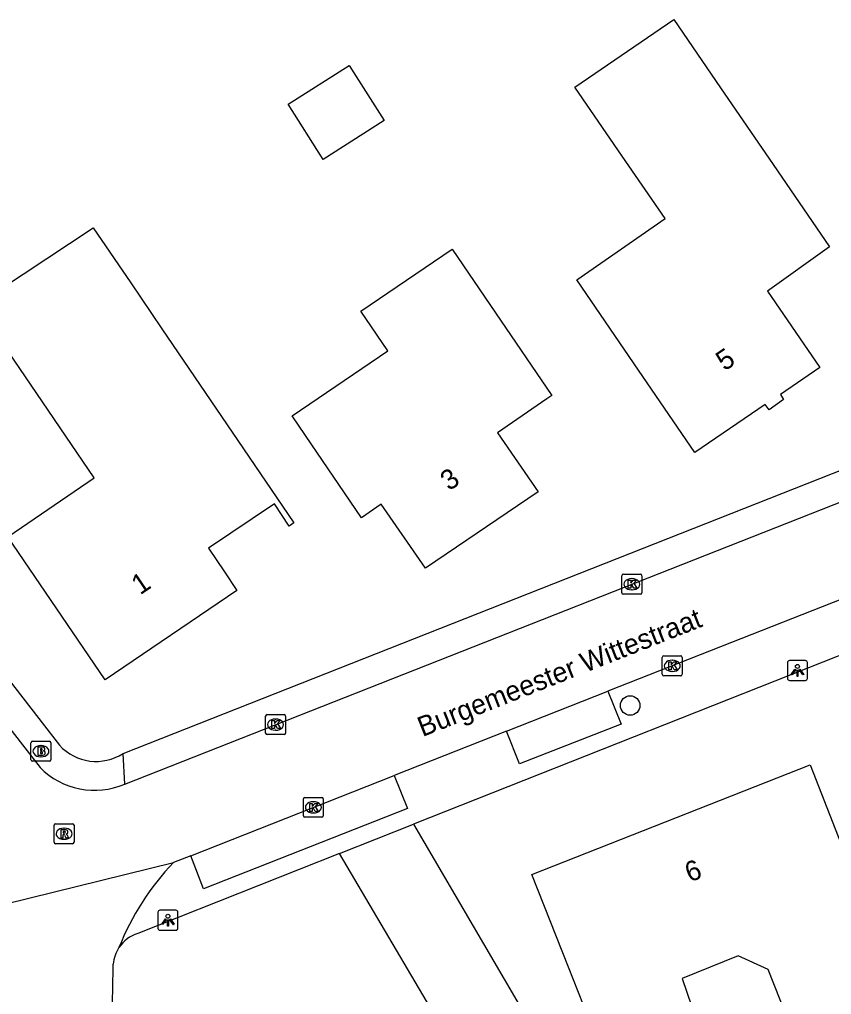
# Model space of a CAD drawing. Extents: x 159503 to 160347, y 382525 to 383272.
# Drawn here: x 159799.95 to 159840.68, y 382910.37 to 382959.27 of the extents above; entities that cross this region are included whole.
import ezdxf

# ---------------------------------------------------------------- set-up
doc = ezdxf.new("R2010")
doc.units = 0
for name, color, linetype in [('IMGEO_Boom', 7, 'Continuous'), ('IMGEO_Brandkraan', 7, 'Continuous'), ('IMGEO_Groenvoorziening', 7, 'Continuous'), ('IMGEO_Kolk', 7, 'Continuous'), ('IMGEO_Lichtpunt', 7, 'Continuous'), ('IMGEO_Openbare_ruimte_label', 7, 'Continuous'), ('IMGEO_Pand', 7, 'Continuous'), ('IMGEO_Pand_nummerreeks', 7, 'Continuous'), ('IMGEO_Rijbaan_lokaal_open', 7, 'Continuous'), ('IMGEO_Rioolput', 7, 'Continuous'), ('IMGEO_Voetpad_open', 7, 'Continuous')]:
    doc.layers.add(name, color=color, linetype=linetype)

msp = doc.modelspace()

# ---------------------------------------------------------------- linework, layer by layer
at = {"layer": 'IMGEO_Boom'}
msp.add_circle((159830.58, 382924.866), 0.489, dxfattribs=at)
at = {"layer": 'IMGEO_Brandkraan'}
for p, q in [((159800.523, 382922.147), (159800.523, 382922.999)), ((159800.598, 382923.073), (159801.45, 382923.073)), ((159801.524, 382922.999), (159801.524, 382922.147)), ((159801.011, 382922.853), (159801.036, 382922.853)), ((159801.45, 382922.073), (159800.598, 382922.073)), ((159801.034, 382922.293), (159801.009, 382922.293))]:
    msp.add_line(p, q, dxfattribs=at)
for points in [[(159800.523, 382922.147), (159800.523, 382922.999)], [(159800.598, 382923.073), (159801.45, 382923.073)], [(159801.524, 382922.999), (159801.524, 382922.147)], [(159800.871, 382922.773), (159800.871, 382922.373), (159801.084, 382922.373)], [(159801.102, 382922.773), (159800.871, 382922.773)], [(159801.05, 382922.692), (159800.996, 382922.692), (159800.996, 382922.616)], [(159800.996, 382922.616), (159801.049, 382922.616)], [(159801.058, 382922.54), (159800.996, 382922.54), (159800.996, 382922.459)], [(159800.996, 382922.459), (159801.058, 382922.459)], [(159801.45, 382922.073), (159800.598, 382922.073)]]:
    msp.add_lwpolyline(points, dxfattribs=at)
for centre, radius, start, end in [((159800.6, 382922.997), 0.0765, 91.552, 178.448), ((159800.6, 382922.997), 0.0765, 91.552, 178.448), ((159801.448, 382922.997), 0.0765, 1.552, 88.448), ((159801.448, 382922.997), 0.0765, 1.552, 88.448), ((159801.051, 382922.654), 0.0379, 267.8285, 90.9355), ((159801.059, 382922.499), 0.0404, 269.8759, 90.5077), ((159801.09, 382922.624), 0.251, 268.6676, 293.5347), ((159801.106, 382922.628), 0.145, 59.4692, 91.5367), ((159801.131, 382922.675), 0.0922, 285.5137, 58.1501), ((159801.136, 382922.483), 0.105, 301.3115, 78.989), ((159800.6, 382922.149), 0.0765, 181.552, 268.448), ((159800.6, 382922.149), 0.0765, 181.552, 268.448), ((159801.448, 382922.149), 0.0765, 271.552, 358.448), ((159801.448, 382922.149), 0.0765, 271.552, 358.448)]:
    msp.add_arc(centre, radius, start, end, dxfattribs=at)
for centre, major_axis, ratio, start_param, end_param in [((159801.01, 382922.573), (-0.387, 0.002), 0.722429, 4.712389, 7.853982), ((159801.035, 382922.573), (-0.39, 0.002), 0.717154, 1.570796, 4.712389)]:
    msp.add_ellipse(centre, major_axis=major_axis, ratio=ratio, start_param=start_param, end_param=end_param, dxfattribs=at)
at = {"layer": 'IMGEO_Groenvoorziening'}
for points in [[(159819.719, 382918.916), (159824.775, 382910.258), (159825.57, 382908.897)], [(159822.273, 382906.815), (159816, 382917.445)]]:
    msp.add_lwpolyline(points, dxfattribs=at)
at = {"layer": 'IMGEO_Kolk'}
for p, q in [((159830.163, 382930.523), (159830.163, 382931.375)), ((159830.238, 382931.449), (159831.09, 382931.449)), ((159830.651, 382931.229), (159830.676, 382931.229)), ((159831.164, 382931.375), (159831.164, 382930.523)), ((159831.09, 382930.449), (159830.238, 382930.449)), ((159830.674, 382930.669), (159830.649, 382930.669)), ((159832.191, 382926.429), (159832.191, 382927.281)), ((159832.266, 382927.355), (159833.118, 382927.355)), ((159833.192, 382927.281), (159833.192, 382926.429)), ((159832.679, 382927.135), (159832.704, 382927.135)), ((159833.118, 382926.355), (159832.266, 382926.355)), ((159832.702, 382926.575), (159832.677, 382926.575)), ((159812.366, 382924.407), (159813.218, 382924.407)), ((159812.291, 382923.481), (159812.291, 382924.333)), ((159812.779, 382924.187), (159812.804, 382924.187)), ((159813.292, 382924.333), (159813.292, 382923.481)), ((159813.218, 382923.407), (159812.366, 382923.407)), ((159812.802, 382923.627), (159812.777, 382923.627)), ((159814.186, 382919.332), (159814.186, 382920.184)), ((159814.261, 382920.258), (159815.113, 382920.258)), ((159814.674, 382920.038), (159814.699, 382920.038)), ((159815.187, 382920.184), (159815.187, 382919.332)), ((159814.697, 382919.478), (159814.672, 382919.478)), ((159815.113, 382919.258), (159814.261, 382919.258))]:
    msp.add_line(p, q, dxfattribs=at)
for points in [[(159830.163, 382930.523), (159830.163, 382931.375)], [(159830.238, 382931.449), (159831.09, 382931.449)], [(159831.164, 382931.375), (159831.164, 382930.523)], [(159830.484, 382931.149), (159830.607, 382931.149), (159830.607, 382930.998), (159830.737, 382931.149), (159830.901, 382931.149), (159830.755, 382930.998), (159830.908, 382930.749), (159830.756, 382930.749), (159830.671, 382930.913), (159830.607, 382930.846), (159830.607, 382930.749), (159830.484, 382930.749), (159830.484, 382931.149)], [(159831.09, 382930.449), (159830.238, 382930.449)], [(159832.191, 382926.429), (159832.191, 382927.281)], [(159832.266, 382927.355), (159833.118, 382927.355)], [(159833.192, 382927.281), (159833.192, 382926.429)], [(159832.512, 382927.055), (159832.635, 382927.055), (159832.635, 382926.904), (159832.765, 382927.055), (159832.929, 382927.055), (159832.783, 382926.904), (159832.936, 382926.655), (159832.784, 382926.655), (159832.699, 382926.819), (159832.635, 382926.752), (159832.635, 382926.655), (159832.512, 382926.655), (159832.512, 382927.055)], [(159833.118, 382926.355), (159832.266, 382926.355)], [(159812.366, 382924.407), (159813.218, 382924.407)], [(159812.291, 382923.481), (159812.291, 382924.333)], [(159812.612, 382924.107), (159812.735, 382924.107), (159812.735, 382923.956), (159812.865, 382924.107), (159813.029, 382924.107), (159812.883, 382923.956), (159813.036, 382923.707), (159812.884, 382923.707), (159812.799, 382923.871), (159812.735, 382923.804), (159812.735, 382923.707), (159812.612, 382923.707), (159812.612, 382924.107)], [(159813.292, 382924.333), (159813.292, 382923.481)], [(159813.218, 382923.407), (159812.366, 382923.407)], [(159814.186, 382919.332), (159814.186, 382920.184)], [(159814.261, 382920.258), (159815.113, 382920.258)], [(159814.507, 382919.958), (159814.63, 382919.958), (159814.63, 382919.807), (159814.76, 382919.958), (159814.924, 382919.958), (159814.778, 382919.807), (159814.931, 382919.558), (159814.779, 382919.558), (159814.694, 382919.722), (159814.63, 382919.655), (159814.63, 382919.558), (159814.507, 382919.558), (159814.507, 382919.958)], [(159815.187, 382920.184), (159815.187, 382919.332)], [(159815.113, 382919.258), (159814.261, 382919.258)]]:
    msp.add_lwpolyline(points, dxfattribs=at)
for centre, start, end in [((159830.24, 382931.373), 91.552, 178.448), ((159830.24, 382931.373), 91.552, 178.448), ((159831.088, 382931.373), 1.552, 88.448), ((159831.088, 382931.373), 1.552, 88.448), ((159830.24, 382930.525), 181.552, 268.448), ((159830.24, 382930.525), 181.552, 268.448), ((159831.088, 382930.525), 271.552, 358.448), ((159831.088, 382930.525), 271.552, 358.448), ((159832.268, 382927.279), 91.552, 178.448), ((159832.268, 382927.279), 91.552, 178.448), ((159833.116, 382927.279), 1.552, 88.448), ((159833.116, 382927.279), 1.552, 88.448), ((159832.268, 382926.431), 181.552, 268.448), ((159832.268, 382926.431), 181.552, 268.448), ((159833.116, 382926.431), 271.552, 358.448), ((159833.116, 382926.431), 271.552, 358.448), ((159812.368, 382924.331), 91.552, 178.448), ((159812.368, 382924.331), 91.552, 178.448), ((159813.216, 382924.331), 1.552, 88.448), ((159813.216, 382924.331), 1.552, 88.448), ((159812.368, 382923.483), 181.552, 268.448), ((159812.368, 382923.483), 181.552, 268.448), ((159813.216, 382923.483), 271.552, 358.448), ((159813.216, 382923.483), 271.552, 358.448), ((159814.263, 382920.182), 91.552, 178.448), ((159814.263, 382920.182), 91.552, 178.448), ((159815.111, 382920.182), 1.552, 88.448), ((159815.111, 382920.182), 1.552, 88.448), ((159814.263, 382919.334), 181.552, 268.448), ((159814.263, 382919.334), 181.552, 268.448), ((159815.111, 382919.334), 271.552, 358.448), ((159815.111, 382919.334), 271.552, 358.448)]:
    msp.add_arc(centre, 0.0765, start, end, dxfattribs=at)
for centre, major_axis, ratio, start_param, end_param in [((159830.65, 382930.949), (-0.387, 0.002), 0.722429, 4.712389, 7.853982), ((159830.675, 382930.949), (-0.39, 0.002), 0.717154, 1.570796, 4.712389), ((159832.678, 382926.855), (-0.387, 0.002), 0.722429, 4.712389, 7.853982), ((159832.703, 382926.855), (-0.39, 0.002), 0.717154, 1.570796, 4.712389), ((159812.778, 382923.907), (-0.387, 0.002), 0.722429, 4.712389, 7.853982), ((159812.803, 382923.907), (-0.39, 0.002), 0.717154, 1.570796, 4.712389), ((159814.673, 382919.758), (-0.387, 0.002), 0.722429, 4.712389, 7.853982), ((159814.698, 382919.758), (-0.39, 0.002), 0.717154, 1.570796, 4.712389)]:
    msp.add_ellipse(centre, major_axis=major_axis, ratio=ratio, start_param=start_param, end_param=end_param, dxfattribs=at)
at = {"layer": 'IMGEO_Lichtpunt'}
for p, q in [((159838.473, 382927.027), (159838.473, 382926.22)), ((159838.473, 382927.027), (159838.473, 382926.22)), ((159839.375, 382927.122), (159838.567, 382927.122)), ((159839.375, 382927.122), (159838.567, 382927.122)), ((159839.469, 382926.22), (159839.469, 382927.027)), ((159839.469, 382926.22), (159839.469, 382927.027)), ((159838.567, 382926.126), (159839.375, 382926.126)), ((159838.567, 382926.126), (159839.375, 382926.126)), ((159807.794, 382914.596), (159806.986, 382914.596)), ((159807.794, 382914.596), (159806.986, 382914.596)), ((159806.892, 382914.501), (159806.892, 382913.694)), ((159806.892, 382914.501), (159806.892, 382913.694)), ((159807.888, 382913.694), (159807.888, 382914.501)), ((159807.888, 382913.694), (159807.888, 382914.501)), ((159806.986, 382913.6), (159807.794, 382913.6)), ((159806.986, 382913.6), (159807.794, 382913.6))]:
    msp.add_line(p, q, dxfattribs=at)
for points in [[(159838.847, 382926.691), (159838.886, 382926.663), (159838.698, 382926.401), (159838.66, 382926.428), (159838.847, 382926.691)], [(159838.949, 382926.643), (159838.996, 382926.643), (159838.996, 382926.321), (159838.949, 382926.321), (159838.949, 382926.643)], [(159839.059, 382926.663), (159839.097, 382926.69), (159839.284, 382926.428), (159839.245, 382926.4), (159839.059, 382926.663)], [(159807.266, 382914.165), (159807.305, 382914.137), (159807.117, 382913.875), (159807.079, 382913.902), (159807.266, 382914.165)], [(159807.368, 382914.117), (159807.415, 382914.117), (159807.415, 382913.795), (159807.368, 382913.795), (159807.368, 382914.117)], [(159807.478, 382914.137), (159807.516, 382914.164), (159807.703, 382913.902), (159807.664, 382913.874), (159807.478, 382914.137)]]:
    msp.add_lwpolyline(points, dxfattribs=at)
for centre in [(159838.972, 382926.825), (159807.391, 382914.299)]:
    msp.add_circle(centre, 0.0994, dxfattribs=at)
for centre, start, end in [((159838.567, 382927.027), 90, 180), ((159838.567, 382927.027), 90, 180), ((159839.375, 382927.027), 0, 90), ((159839.375, 382927.027), 0, 90), ((159838.567, 382926.22), 180, 270), ((159838.567, 382926.22), 180, 270), ((159839.375, 382926.22), 270, 0), ((159839.375, 382926.22), 270, 360), ((159806.986, 382914.501), 90, 180), ((159806.986, 382914.501), 90, 180), ((159807.794, 382914.501), 0, 90), ((159807.794, 382914.501), 0, 90), ((159806.986, 382913.694), 180, 270), ((159806.986, 382913.694), 180, 270), ((159807.794, 382913.694), 270, 0), ((159807.794, 382913.694), 270, 360)]:
    msp.add_arc(centre, 0.0946, start, end, dxfattribs=at)
at = {"layer": 'IMGEO_Pand'}
for points in [[(159832.762, 382959.268), (159835.116, 382955.835), (159837.748, 382951.997), (159840.576, 382947.873), (159837.474, 382945.651), (159840.098, 382941.809), (159838.121, 382940.456), (159838.275, 382940.209), (159837.549, 382939.692), (159837.359, 382939.953), (159833.819, 382937.55), (159831, 382941.681), (159827.903, 382946.22), (159832.335, 382949.291), (159830.175, 382952.411), (159827.804, 382955.868), (159832.762, 382959.268)], [(159816.49, 382956.966), (159818.245, 382954.196), (159815.182, 382952.255), (159813.426, 382955.025), (159816.49, 382956.966)], [(159807.09, 382943.762), (159810.9, 382938.157), (159813.711, 382934.022), (159813.481, 382933.854), (159812.732, 382934.98), (159809.429, 382932.761), (159810.232, 382931.566), (159810.856, 382930.637), (159804.242, 382926.147), (159799.36, 382933.326), (159803.7, 382936.281), (159799.681, 382942.183), (159797.796, 382944.952), (159803.648, 382948.828), (159805.528, 382946.062), (159807.09, 382943.762)], [(159826.646, 382940.418), (159826.404, 382940.241), (159823.924, 382938.546), (159825.958, 382935.584), (159820.316, 382931.756), (159818.093, 382934.961), (159817.109, 382934.282), (159814.294, 382938.414), (159813.628, 382939.392), (159818.417, 382942.652), (159817.066, 382944.633), (159821.648, 382947.753), (159823.831, 382944.55), (159826.646, 382940.418)], [(159846.866, 382903.296), (159840.225, 382900.649), (159837.9, 382906.568), (159838.747, 382908.507), (159837.494, 382911.622), (159836, 382912.309), (159833.186, 382911.18), (159833.664, 382909.806), (159828.984, 382907.938), (159827.481, 382911.745), (159825.644, 382916.395), (159839.605, 382921.884), (159841.424, 382917.227), (159846.866, 382903.296)]]:
    msp.add_lwpolyline(points, dxfattribs=at)
at = {"layer": 'IMGEO_Rijbaan_lokaal_open'}
for points in [[(159773.929, 382959.054), (159781.987, 382948.65), (159795.756, 382930.872), (159801.595, 382923.334), (159801.952, 382922.871)], [(159772.631, 382958.244), (159800.442, 382922.436), (159800.976, 382921.759)], [(159805.148, 382922.46), (159871.857, 382948.784)], [(159805.224, 382920.924), (159850.691, 382938.839)], [(159846.419, 382932.259), (159829.466, 382925.58)], [(159824.384, 382923.582), (159829.466, 382925.58)], [(159824.384, 382923.582), (159818.738, 382921.356)], [(159805.224, 382920.924), (159805.148, 382922.46)], [(159808.536, 382917.335), (159818.738, 382921.356)], [(159808.536, 382917.335), (159807.664, 382916.991)], [(159798.017, 382914.622), (159807.664, 382916.991)]]:
    msp.add_lwpolyline(points, dxfattribs=at)
for centre, radius, start, end in [((159803.794, 382924.566), 2.504, 222.6159, 302.7282), ((159803.714, 382924.467), 3.851, 224.6802, 293.0789), ((159817.242, 382907.863), 13.231, 136.3787, 158.4499), ((159806.437, 382911.725), 1.802, 146.3718, 174.3912), ((159750.82, 382912.013), 53.823, 352.4298, 359.881)]:
    msp.add_arc(centre, radius, start, end, dxfattribs=at)
at = {"layer": 'IMGEO_Rioolput'}
for p, q in [((159801.681, 382918.009), (159801.681, 382918.861)), ((159801.756, 382918.935), (159802.608, 382918.935)), ((159802.169, 382918.715), (159802.194, 382918.715)), ((159802.682, 382918.861), (159802.682, 382918.009)), ((159802.192, 382918.155), (159802.167, 382918.155)), ((159802.608, 382917.935), (159801.756, 382917.935))]:
    msp.add_line(p, q, dxfattribs=at)
for points in [[(159801.681, 382918.009), (159801.681, 382918.861)], [(159801.756, 382918.935), (159802.608, 382918.935)], [(159802.27, 382918.633), (159802.018, 382918.635), (159802.018, 382918.235)], [(159802.196, 382918.554), (159802.142, 382918.554), (159802.142, 382918.473)], [(159802.142, 382918.473), (159802.194, 382918.473)], [(159802.682, 382918.861), (159802.682, 382918.009)], [(159802.018, 382918.235), (159802.142, 382918.235), (159802.142, 382918.397), (159802.153, 382918.397)], [(159802.2, 382918.368), (159802.271, 382918.235), (159802.411, 382918.235), (159802.346, 382918.361)], [(159802.608, 382917.935), (159801.756, 382917.935)]]:
    msp.add_lwpolyline(points, dxfattribs=at)
for centre, radius, start, end in [((159801.758, 382918.859), 0.0765, 91.552, 178.448), ((159801.758, 382918.859), 0.0765, 91.552, 178.448), ((159802.178, 382918.662), 0.19, 274.7715, 282.9687), ((159802.202, 382918.458), 0.0964, 77.0061, 93.1865), ((159802.216, 382918.515), 0.0378, 276.6634, 79.6772), ((159802.269, 382918.523), 0.109, 350.3612, 89.416), ((159802.267, 382918.523), 0.112, 277.5842, 350.9817), ((159802.606, 382918.859), 0.0765, 1.552, 88.448), ((159802.606, 382918.859), 0.0765, 1.552, 88.448), ((159801.758, 382918.011), 0.0765, 181.552, 268.448), ((159801.758, 382918.011), 0.0765, 181.552, 268.448), ((159802.152, 382918.344), 0.0533, 26.0293, 88.6989), ((159802.251, 382918.308), 0.108, 29.5134, 73.7905), ((159802.606, 382918.011), 0.0765, 271.552, 358.448), ((159802.606, 382918.011), 0.0765, 271.552, 358.448)]:
    msp.add_arc(centre, radius, start, end, dxfattribs=at)
for centre, major_axis, ratio, start_param, end_param in [((159802.168, 382918.435), (-0.387, 0.002), 0.722429, 4.712389, 7.853982), ((159802.193, 382918.435), (-0.39, 0.002), 0.717154, 1.570796, 4.712389)]:
    msp.add_ellipse(centre, major_axis=major_axis, ratio=ratio, start_param=start_param, end_param=end_param, dxfattribs=at)
at = {"layer": 'IMGEO_Voetpad_open'}
for points in [[(159876.5, 382941.374), (159819.719, 382918.916)], [(159829.466, 382925.58), (159830.133, 382923.927), (159825.032, 382921.94), (159824.384, 382923.582)], [(159818.738, 382921.356), (159819.408, 382919.703), (159809.177, 382915.674), (159808.536, 382917.335)], [(159816, 382917.445), (159819.719, 382918.916)], [(159816, 382917.445), (159805.876, 382913.439)]]:
    msp.add_lwpolyline(points, dxfattribs=at)
msp.add_arc((159806.442, 382911.721), 1.809, 108.2338, 146.3594, dxfattribs=at)

# ---------------------------------------------------------------- texts
at = {"layer": 'IMGEO_Openbare_ruimte_label'}
msp.add_text('Burgemeester Wittestraat', height=1, rotation=21.5354, dxfattribs=at).set_placement((159820.16, 382923.281))
at = {"layer": 'IMGEO_Pand_nummerreeks'}
for s, rotation, p in [('5', 34.1488, (159835.316, 382941.61)), ('3', 34.154, (159821.494, 382935.601)), ('1', 34.1712, (159806, 382930.386)), ('6', 21.4631, (159833.568, 382915.987))]:
    msp.add_text(s, height=1, rotation=rotation, dxfattribs=at).set_placement(p)

doc.saveas('drawing.dxf')
